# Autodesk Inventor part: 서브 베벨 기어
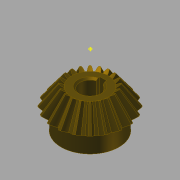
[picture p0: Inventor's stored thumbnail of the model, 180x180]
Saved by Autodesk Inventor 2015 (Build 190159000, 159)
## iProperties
Created: 2014-10
Part Number: 서브 베벨 기어
Material: 강철, 탄소
Document SubType Name: Modeling
Designer: KYOUNG IL JANG
Categories: <?xml version="1.0" encoding="UTF-16"?> <MemberInstance><Categories><FamilyTemplate><FamilyTemplateParameter ValueType="xs:double" Id="1" ObjectReferenceKey="da
Mass: 135.037 g
Surface Area: 63.6518 cm^2
Volume: 17.1585 cm^3
Density: 7.87 g/cm^3
Appearance: Brindle
CustomPartVersion: 1
Author: SeoGD™ [www.esajin.kr]
Revision Number: 1
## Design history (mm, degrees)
node "맨 위 점"
node "메쉬 평면2"
sketch "톱니 본체 스케치"
  geometry: L1 (0, 0)-(18.003, -31.331); L2 (18.003, -31.331)-(21.664, -28.891); L3 (21.664, -28.891)-(0, 0); L4 (20, -30)-(0, 0); L5 (10.813, -18.818)-(13.012, -17.352); L6 (18.003, -31.331)-(10.813, -18.818); L7 (21.664, -28.891)-(13.012, -17.352); L8 (0, -39.387)-(0, 6.564) reference; L9 (0, -30)-(21.664, -30)
  constraints: 16 end point, 4 point on line, 3 perpendicular, 2 collinear, 1 horizontal alignment, 1 vertical alignment
  dimensions: "d0" = 40 diameter of L4.start L8 (= da_de); "d1" = 36.00616 diameter of L1.end L8 (= da_dfe); "d2" = 43.3282 diameter of L2.end L8 (= da_dae); "d3" = 14.4 distance between parallel lines of L2 L5 (= da_b); "d4" = 28.8906 vertical distance of L2.end L1.start (= da_ve)
revolve "톱니 본체" sketch "톱니 본체 스케치" stored, may be unused: angle "d5" = 90 deg
node "시작점"
node "톱니 평면"
sketch "시작 스케치"
  geometry: L1 (0, -23.505)-(0, 10.645) reference; L2 (-0.834, -2.928)-(0.834, -2.928); A1 r 8.898 centre (-9.698, -3.713) between (-0.834, -2.928) and (-3.903, 3.04); A2 r 8.898 centre (9.698, -3.713) between (3.903, 3.04) and (0.834, -2.928); A3 r 27.357 centre (0, -24.037) between (3.903, 3.04) and (-3.903, 3.04); 1 further point
  constraints: 6 point on circle, 3 centre point, 3 symmetric about line, 2 end point, 1 coincident, 1 perpendicular, 1 other
  dimensions: "d7" = 8.89846 radius of A1 (= fd_rr); "d8" = 9.69794 horizontal distance of point (0, -24.037) A1.centre (= fd_x); "d9" = 20.32439 vertical distance of point (0, -24.037) A1.centre (= fd_y); "d57" = 27.35701 radius of A3 (= 0.5 x fd_dva + 0.3 x da_he); "d58" = 21.10901 distance from line of A3.centre L2 (= 0.5 x fd_dva - 1.12 x da_he)
node "끝점"
  node "끝 평면"
sketch "3D 스케치 오른쪽"
  node "Helical Curve Right" dims "d65" = 229.90621 (computed from da_dm, da_delta, da_beta), "d66" = 31.5, "d67" = 40 (= da_de), "d68" = -5.88003 (= -da_delta), "d69" = 12.16458 (computed from fd_loft, da_delta)
node "끝 평면 오른쪽"
sketch "끝 스케치 오른쪽"
  geometry: L1 (0, -22.649)-(0, 12.15) reference; L2 (-0.497, -1.72)-(0.497, -1.72); A1 r 5.299 centre (-5.775, -2.187) between (-0.497, -1.72) and (-2.324, 1.834); A2 r 5.299 centre (5.775, -2.187) between (2.324, 1.834) and (0.497, -1.72); A3 r 16.291 centre (0, -14.29) between (2.324, 1.834) and (-2.324, 1.834); 1 further point
  constraints: 6 point on circle, 3 centre point, 3 symmetric about line, 2 end point, 1 coincident, 1 perpendicular, 1 other
  dimensions: "d70" = 5.77526 horizontal distance of A3.centre A1.centre (computed from fd_x, fd_ratio); "d71" = 12.10346 vertical distance of point (0, -14.29) A1.centre (computed from fd_y, fd_ratio); "d72" = 5.29916 radius of A1 (computed from fd_rr, fd_ratio); "d73" = 12.57071 distance from line of point (0, -14.29) L2 (computed from d58, fd_ratio); "d74" = 16.29149 radius of A3 (computed from d57, fd_ratio)
feature "로프트 오른쪽" sketch "끝 스케치 오른쪽" dims "d75" = 0, "d77" = 0, "d79" = 0, "d80" = 90 deg, "d85" = 20, "d92" = 90 deg, "d93" = 90 deg, "da_teethtype" = 0 [user parameter]
sketch "3D 스케치 왼쪽"
  node "Helical Curve Left" dims "d26" = 229.90621 (computed from da_dm, da_delta, da_beta), "d27" = 12.16458 (computed from fd_loft, da_delta), "d28" = 40 (= da_de), "d29" = -5.88003 (= -da_delta)
node "끝 평면 왼쪽"
sketch "끝 스케치 왼쪽" dims "d56" = 10.82768 (derived)
  geometry: L1 (0, -35.087)-(0, 18.089) reference; L2 (-0.497, -1.716)-(0.497, -1.716); A1 r 5.299 centre (-5.775, -2.183) between (-0.497, -1.716) and (-2.324, 1.838); A2 r 5.299 centre (5.775, -2.183) between (2.324, 1.838) and (0.497, -1.716); A3 r 16.291 centre (0, -14.287) between (2.324, 1.838) and (-2.324, 1.838); 2 further points; 1 other entity
  constraints: 6 point on circle, 3 centre point, 3 symmetric about line, 2 end point, 1 coincident, 2 other
  dimensions: "d30" = 5.29916 radius of A1 (computed from fd_rr, fd_ratio); "d31" = 5.77526 horizontal distance of point (0, -14.287) A1.centre (computed from fd_x, fd_ratio); "d32" = 12.10346 vertical distance of A1.centre point (0, -14.287) (computed from fd_y, fd_ratio); "d61" = 16.29149 radius of A3 (computed from d57, fd_ratio); "d62" = 12.57071 distance from line of point (0, -14.287) L2 (computed from d58, fd_ratio)
feature "로프트 왼쪽" sketch "끝 스케치 왼쪽" dims "d35" = 0, "d37" = 0, "d39" = 0, "d40" = 90 deg, "d84" = 10, "d90" = 90 deg, "d91" = 90 deg, "da_teethtype" = 0 [user parameter]
sketch "본체 스케치"
  geometry: L1 (0, -35.038)-(0, -19.531) reference; L2 (18.003, -31.331)-(10.813, -18.818) reference; L3 (10.813, -18.818)-(0, -18.818); L4 (18.003, -31.331)-(0, -31.331)
  constraints: 4 end point, 2 perpendicular, 2 point on line
revolve "본체 고정" sketch "본체 스케치" stored, may be unused: angle "d46" = 90 deg
feature "피치 지름" dims angle "d47" = 90 deg
sketch "스케치8"
  geometry: C1 r 17 at (0, 0); 1 further point
  constraints: 1 centre point, 1 coincident
  dimensions: "d94" = 34 diameter of C1
extrude "돌출1" join sketch "스케치8" distance "d95" = 10; taper "d96" = 0 deg
sketch "스케치9"
  geometry: 1 further point
hole "구멍1" sketch "스케치9" at (0, 0) diameter "d97" = 12; stored, may be unused: countersink angle "d101" = 90 deg, drill point angle "d103" = 118 deg; dims "d98" = 6, "d99" = 4, "d100" = 2, "d102" = 8
sketch "스케치10"
  geometry: 1 further point
sketch "스케치11"
  geometry: 1 further point
sketch "스케치12"
  geometry: L1 (-2, 5.657)-(-2, 7.8); L2 (-2, 7.8)-(2, 7.8); L3 (2, 7.8)-(2, 5.657); A1 r 6 centre (0, 0) between (-2, 5.657) and (2, 5.657) reference; 1 further point
  constraints: 6 end point, 2 parallel, 2 point on circle, 1 perpendicular, 1 vertical
  dimensions: "d104" = 4 distance of L1.end L2.end; "d105" = 13.8 dimension on A1 L2
extrude "돌출2" cut sketch "스케치12" stored distance "d106" = 7; taper "d107" = 0 deg
chamfer "모따기1" distance "d108" = 1; stored, may be unused: second distance "d109" = 2, angle "d110" = 45 deg
body "Solid1"
feature "로프트" dims "d17" = 0, "d18" = 90 deg, "d19" = 0, "d20" = 90 deg, "d89" = 0, "da_teethtype" = 0 [user parameter]
pattern_circular "원형 패턴" dims angle "d22" = 360 deg, "d88" = 0, "da_teethtype" = 0 [user parameter]
pattern_circular "원형 패턴 오른쪽" dims angle "d82" = 360 deg, "da_teethtype" = 0 [user parameter]
pattern_circular "원형 패턴 왼쪽" dims angle "d42" = 360 deg, "da_teethtype" = 0 [user parameter]
sketch "끝 스케치"
  geometry: L1 (0, -15.359)-(0, 6.983) reference; L2 (-0.497, -1.72)-(0.497, -1.72); A1 r 5.299 centre (-5.775, -2.187) between (-0.497, -1.72) and (-2.324, 1.834); A2 r 5.299 centre (5.775, -2.187) between (2.324, 1.834) and (0.497, -1.72); A3 r 16.291 centre (0, -14.29) between (2.324, 1.834) and (-2.324, 1.834); 1 further point
  constraints: 6 point on circle, 3 centre point, 3 symmetric about line, 2 end point, 1 coincident, 1 other
  dimensions: "d12" = 5.29916 radius of A1 (computed from fd_rr, fd_ratio); "d15" = 5.77526 horizontal distance of A1.centre point (0, -14.29) (computed from fd_x, fd_ratio); "d16" = 12.10346 vertical distance of A1.centre point (0, -14.29) (computed from fd_y, fd_ratio); "d59" = 16.29149 radius of A3 (computed from d57, fd_ratio); "d60" = 12.57071 distance from line of A3.centre L2 (computed from d58, fd_ratio)
sketch "Sketch6"
  geometry: L1 (20, -30)-(0, 0) reference; L2 (0, -37.8)-(0, 6.3) reference
body "Srf1"
other parameters: "da_b" = 14.4 [user parameter; used in 2 equation terms], "da_de" = 40 [user parameter; used in 4 equation terms], "da_dae" = 43.3282 [user parameter; used in 2 equation terms], "da_dfe" = 36.00616 [user parameter; used in 1 equation term], "da_le" = 36.05551 [user parameter; used in 1 equation term], "da_omega" = 90 deg [user parameter; used in 1 equation term], "da_beta" = 0 [user parameter; used in 2 equation terms], "da_delta" = 5.88003 [user parameter; used in 8 equation terms], "da_alpha" = 20 deg [user parameter; used in 2 equation terms], "da_he" = 4.4 [user parameter; used in 4 equation terms], "da_ve" = 28.8906 [user parameter; used in 1 equation term], "fd_dv" = 48.07402 (computed from da_de, da_delta) [user parameter; used in 1 equation term], "fd_dva" = 52.07402 (computed from da_dae, da_delta) [user parameter; used in 3 equation terms], "fd_dvb" = 45.1748 (computed from fd_dv, da_alpha) [user parameter; used in 2 equation terms], "da_zv" = 240.37008 [user parameter; used in 1 equation term], "fd_loft" = 14.62 (= da_b + 0.05 x da_he) [user parameter; used in 4 equation terms], "fd_ratio" = 5.95514 (computed from da_le, fd_loft) [user parameter; used in 15 equation terms], "fd_rr" = 8.89846 (computed from fd_dd, fd_dvb) [user parameter; used in 6 equation terms], "fd_angle" = 0.66075 (computed from da_zv) [user parameter; used in 4 equation terms], "fd_x1" = 1.58709 (computed from da_dvw, fd_angle) [user parameter; used in 1 equation term], "fd_y1" = 23.98456 (computed from da_dvw, fd_angle) [user parameter; used in 1 equation term], "fd_x2" = 8.11084 (computed from fd_rr, fd_angle2, fd_angle) [user parameter; used in 1 equation term], "fd_y2" = 3.66016 (computed from fd_rr, fd_angle2, fd_angle) [user parameter; used in 1 equation term], "fd_x" = 9.69794 (= fd_x1 + fd_x2) [user parameter; used in 4 equation terms], "fd_y" = 20.32439 (= fd_y1 - fd_y2) [user parameter; used in 4 equation terms], "fd_angle2" = 3.57832 (computed from fd_dvb, fd_dd, da_alpha) [user parameter; used in 2 equation terms], "fd_dd" = 48.55402 (= fd_dva - 0.8 x da_he) [user parameter; used in 2 equation terms], "da_dvw" = 48.07402 [user parameter; used in 2 equation terms], "d11" = 14.62 (= fd_loft), "da_dm" = 32.01232 [user parameter; used in 2 equation terms], "da_x" = 0 [user parameter], "da_m" = 2 [user parameter], "d48" = 0, "d49" = 0, "d50" = 90 deg (= da_omega), "d51" = 9 deg (computed from da_z), "d52" = 0, "d53" = 0, "d54" = 0
